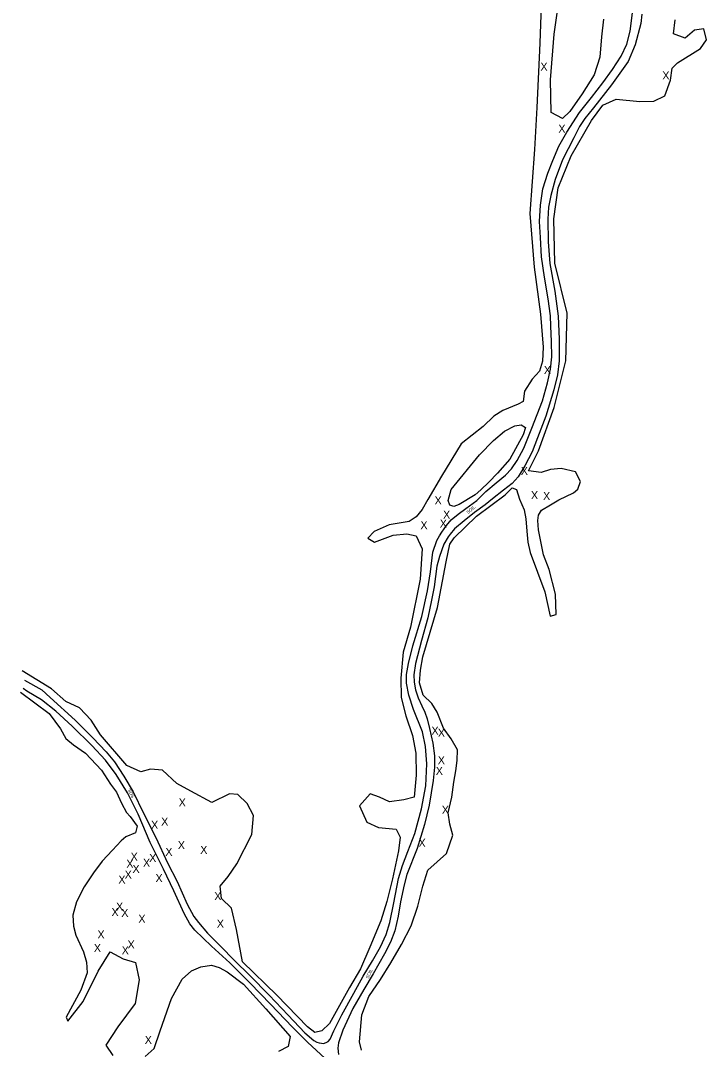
# Model space of a CAD drawing. Extents: x 2030130 to 2036320, y 723205 to 762423.
# Drawn here: x 2031084 to 2031941, y 749317 to 750602 of the extents above; entities that cross this region are included whole.
import ezdxf

# ---------------------------------------------------------------- set-up
doc = ezdxf.new("R2010")
doc.units = 0
for name, color, linetype in [('Draft_Station Labels Major', 7, 'Continuous'), ('Draft_Station Tics Major', 7, 'Continuous'), ('Old_Level_23', 7, 'Continuous')]:
    doc.layers.add(name, color=color, linetype=linetype)

msp = doc.modelspace()

# ---------------------------------------------------------------- linework, layer by layer
at = {"layer": 'Draft_Station Labels Major'}
for points in [[(2031610.3, 749963), (2031616, 749971.2), (2031622.1, 749978.2), (2031630.6, 749985.2), (2031640.2, 749992.3), (2031653.8, 750002.5), (2031665.1, 750013.8), (2031678.3, 750024.7), (2031689.6, 750034.1), (2031697.4, 750041.9), (2031704.2, 750052.6), (2031712.5, 750067.7), (2031722.7, 750092.8), (2031735.8, 750126.8), (2031742.2, 750149.6), (2031746.1, 750166.5), (2031747.6, 750181.8), (2031747.4, 750200.9), (2031746.5, 750220.4), (2031745.8, 750233.2), (2031742.9, 750254.2), (2031738.6, 750281.2), (2031734.8, 750307), (2031733.3, 750330.9), (2031732.4, 750351.1), (2031733.7, 750371.2), (2031736.5, 750391.9), (2031742.7, 750411.2), (2031748.9, 750427.1), (2031756.5, 750445.2), (2031766.4, 750462.5), (2031782.2, 750487.2), (2031797.4, 750505.7), (2031811.2, 750524.3), (2031823.3, 750540.9), (2031834.1, 750557.5), (2031841.4, 750572.3), (2031845.6, 750588.6), (2031848.3, 750611.5)], [(2031859.9, 750609.8), (2031858.7, 750598.1), (2031851.9, 750571.5), (2031842.9, 750550.6), (2031822.3, 750521.7), (2031799.7, 750492.8), (2031789, 750479.4), (2031782.1, 750469.8), (2031775, 750455.5), (2031761.1, 750428), (2031751.7, 750403.3), (2031746.3, 750383.4), (2031743.6, 750369), (2031742.7, 750353.7), (2031742.9, 750325.6), (2031745.3, 750298.4), (2031751.6, 750264.1), (2031755.4, 750232.6), (2031757, 750204.1), (2031757, 750176.7), (2031754.7, 750159.6), (2031750.3, 750140.7), (2031740.1, 750107.9), (2031729.8, 750080.6), (2031723.1, 750063.2), (2031713.8, 750045.9), (2031705.8, 750031.9), (2031698.1, 750023.7), (2031687.2, 750015.5), (2031673.5, 750004.6), (2031664.2, 749996.9), (2031650.9, 749987.6), (2031638, 749976.9), (2031626.1, 749967.1), (2031620.6, 749960.3), (2031618.2, 749956.9)], [(2031088.9, 749778), (2031110.7, 749765.8), (2031121.1, 749756.5), (2031152, 749728.2), (2031174.1, 749706.2), (2031191, 749688.7), (2031201.2, 749675.9), (2031213.1, 749658.2), (2031224.6, 749638.6), (2031237.4, 749612.1), (2031252.8, 749581.7), (2031267.5, 749550), (2031279.6, 749526.7), (2031291.9, 749498.1), (2031300.5, 749482.8), (2031306.4, 749475.4), (2031317.4, 749462), (2031333.8, 749445.9), (2031351.3, 749428.1), (2031370.5, 749409), (2031394.4, 749384.7), (2031418.1, 749359.5), (2031439, 749337.7), (2031450.3, 749327.9), (2031453.9, 749326), (2031456.8, 749325), (2031460.1, 749324.5), (2031462.6, 749324.4), (2031465.6, 749325.4), (2031468.2, 749326.6), (2031470.7, 749329.6), (2031475.5, 749340.2), (2031485.2, 749360.1), (2031500.1, 749387.1), (2031512.1, 749408.5), (2031523.8, 749427.4), (2031533.5, 749444.8), (2031540.6, 749460.5), (2031545.3, 749475.2), (2031550.2, 749500.1), (2031556.1, 749530.5), (2031560.9, 749546.5), (2031567.6, 749564.2), (2031576.6, 749586.6), (2031584.8, 749617.5), (2031590.2, 749646), (2031591.7, 749673.7), (2031590, 749695.3), (2031585.9, 749713.6), (2031574.7, 749741.3), (2031569.2, 749759.2), (2031566.1, 749774.3), (2031566, 749785), (2031568.6, 749798.8), (2031574.2, 749820.8), (2031585.2, 749857.5), (2031592.4, 749889.7), (2031596, 749913.5), (2031599, 749937.9), (2031604.1, 749952.5), (2031607.4, 749958.3), (2031610.3, 749963)], [(2031618.2, 749956.9), (2031612.8, 749947.8), (2031607.3, 749932.7), (2031604.1, 749920.4), (2031600.7, 749894.6), (2031597.2, 749878.1), (2031592.6, 749856), (2031585, 749827.8), (2031577.5, 749798.9), (2031575.3, 749784.8), (2031575.5, 749775.5), (2031577.3, 749766.1), (2031580.8, 749755.9), (2031585.1, 749745.8), (2031589.2, 749737.9), (2031592, 749729.8), (2031594.8, 749717.7), (2031599.1, 749699.3), (2031601.1, 749683.7), (2031601.1, 749669.4), (2031599.5, 749652.8), (2031594.5, 749621.9), (2031588.7, 749597.8), (2031579.6, 749568), (2031566.7, 749535.5), (2031563, 749522.4), (2031558.7, 749501.2), (2031555.5, 749483.1), (2031551.6, 749464.9), (2031546.3, 749451), (2031538.6, 749436.2), (2031524.6, 749411.2), (2031512.7, 749391.7), (2031499, 749367.8), (2031486.7, 749340.8), (2031481, 749325), (2031480.3, 749318.3), (2031481.2, 749310.7)], [(2031464.2, 749305.8), (2031442.7, 749325.6), (2031423.8, 749344.8), (2031396.2, 749373.5), (2031370.9, 749399.6), (2031345.4, 749424.9), (2031322.5, 749446), (2031301.8, 749465.8), (2031295.2, 749473.9), (2031288.4, 749486.7), (2031275.5, 749515), (2031262.3, 749541.9), (2031245.9, 749575.4), (2031230.7, 749610.5), (2031217.4, 749637.4), (2031203.3, 749660.2), (2031190, 749678.3), (2031172.8, 749696.3), (2031148.5, 749720.6), (2031128.1, 749739.2), (2031110.2, 749753.6), (2031091.9, 749764.1), (2031087, 749767.7)]]:
    msp.add_lwpolyline(points, dxfattribs=at)
at = {"layer": 'Draft_Station Tics Major'}
for points in [[(2031736.2, 750667.6), (2031732.7, 750573.7), (2031729, 750493.5), (2031725.9, 750440.9), (2031720.1, 750361.1), (2031725.7, 750294), (2031733.7, 750235.2), (2031736.9, 750193.8), (2031736, 750176.6), (2031732.1, 750163.8), (2031722.9, 750153.9), (2031713.5, 750138.9), (2031711.7, 750126.3), (2031705.7, 750122.9), (2031686.5, 750114.9), (2031675.2, 750108), (2031661.8, 750095), (2031634.4, 750073.1), (2031609.8, 750033), (2031592.8, 750003.6), (2031585.5, 749991.1), (2031578.1, 749981.9), (2031569.4, 749976.1), (2031544.3, 749971.9)], [(2031812.3, 750603.5), (2031809.7, 750581.4), (2031807.7, 750556.4), (2031800.5, 750534.2), (2031785.7, 750510.2), (2031770.2, 750488.4), (2031760.8, 750479.6), (2031746.8, 750486.9), (2031745.8, 750528), (2031750.4, 750585), (2031755.5, 750619.7)], [(2031737.1, 749934.6), (2031730.9, 749965.9), (2031730.3, 749977.3), (2031731, 749984.3), (2031734.8, 749990.3), (2031745.9, 749996.9), (2031756.3, 750003.4), (2031774.7, 750012), (2031780.3, 750016.5), (2031783.6, 750026.3), (2031777.3, 750038.4), (2031759.2, 750042.6), (2031746, 750041.2), (2031734.3, 750037.4), (2031718.6, 750039.5), (2031731.2, 750064.6), (2031750.5, 750118.5), (2031765.2, 750177), (2031766.8, 750236.5), (2031751.6, 750299), (2031750.2, 750354.4), (2031755.5, 750393), (2031771.7, 750432.9), (2031797.2, 750477.2), (2031811.5, 750496.2), (2031828.2, 750503.6), (2031857.5, 750500.7), (2031874.9, 750501.4), (2031888.8, 750508), (2031896, 750527.4), (2031898, 750542.4), (2031904.8, 750549.1), (2031933.2, 750567.1), (2031940.8, 750578), (2031937.5, 750591.5), (2031925.7, 750589.8), (2031914.3, 750580), (2031899.7, 750585.2), (2031901.7, 750603)], [(2031622.1, 750016), (2031657.5, 750059.5), (2031674.7, 750077.2), (2031688.4, 750089), (2031701.5, 750095.7), (2031709.4, 750096.8), (2031714.7, 750093.8), (2031711.9, 750084.5), (2031695.1, 750054.2), (2031679.9, 750036.4), (2031668.8, 750025.2), (2031659.1, 750015.7), (2031651.8, 750009.6)], [(2031651.8, 750009.6), (2031631.9, 749997.5), (2031625.3, 749995.1), (2031620.2, 749996.6), (2031618.2, 750002.4), (2031622.1, 750016)], [(2031625.5, 749956), (2031653.4, 749982.9), (2031689.4, 750009.4), (2031698.2, 750018.4), (2031703.6, 750016.4), (2031707.3, 750004.2), (2031713.3, 749990.8), (2031715, 749979.4), (2031716.6, 749964.1), (2031717.7, 749950.6), (2031720.8, 749937.4)], [(2031544.3, 749971.9), (2031525.9, 749963.6), (2031517.6, 749955.4), (2031526.1, 749950.3), (2031549.5, 749959.3), (2031566.5, 749960.8), (2031578.1, 749958.4), (2031585.6, 749941.9), (2031583.2, 749904.2), (2031571, 749844.2), (2031561.9, 749813.2), (2031559, 749780.4), (2031559.5, 749756.6), (2031565.1, 749733.7), (2031573.7, 749708.8), (2031577.9, 749686.8), (2031578.3, 749659.4), (2031575.5, 749632.1), (2031562.7, 749628.4), (2031544.8, 749626), (2031532.3, 749632.1), (2031520.9, 749636.2), (2031507.5, 749621), (2031516.6, 749600.8), (2031531.3, 749594.1), (2031553.3, 749592.1), (2031558.3, 749582), (2031556.3, 749565), (2031548.5, 749530), (2031541.4, 749501.4), (2031533.9, 749477.6), (2031520.2, 749444.4), (2031508.5, 749417.3), (2031494.7, 749394.1), (2031469.8, 749349.3), (2031460.5, 749340), (2031451.7, 749337.8), (2031442.6, 749345), (2031404.1, 749384.6), (2031361, 749426.3), (2031353.8, 749466.8), (2031347.4, 749493.2), (2031334.9, 749505.4), (2031333.2, 749520.9), (2031343.1, 749533), (2031354.2, 749548.8), (2031372.8, 749585.2), (2031374.9, 749609), (2031367.2, 749623.8), (2031355.4, 749635.4), (2031344.8, 749635.9), (2031322.7, 749625.4), (2031296.5, 749639.6), (2031279.2, 749649.1), (2031261.3, 749665.8), (2031246.4, 749666.7), (2031234.2, 749663.6), (2031216.6, 749671.6), (2031183.8, 749709.9), (2031172.2, 749728.1), (2031157.5, 749743.3), (2031140.6, 749751.4), (2031122.4, 749767.3), (2031086, 749789.5)], [(2031510, 749316.1), (2031507.2, 749326.2), (2031510.2, 749359.9), (2031519, 749382.9), (2031533.6, 749404.2), (2031546.4, 749424.8), (2031560, 749448), (2031572.1, 749471.2), (2031580.4, 749495.9), (2031586.4, 749520.6), (2031592.7, 749540.7), (2031616.2, 749561.6), (2031623.8, 749584.4), (2031620.1, 749598), (2031618.1, 749612.2), (2031622.7, 749632.1), (2031625.1, 749650.7), (2031627.9, 749664.6), (2031629.6, 749677.6), (2031630, 749690.9), (2031621.7, 749704.6), (2031612.2, 749718.2), (2031604.3, 749738.2), (2031597.6, 749749), (2031587, 749759.5), (2031582.5, 749774.6), (2031583.4, 749790.6), (2031586.5, 749807.3), (2031604.9, 749869), (2031615.7, 749925.7), (2031620.1, 749948), (2031625.5, 749956)], [(2031720.8, 749937.4), (2031738.9, 749888.4), (2031745.4, 749858.1), (2031752.9, 749859.9), (2031752.3, 749885.5), (2031744.2, 749916.4), (2031737.1, 749934.6)], [(2031083.9, 749763.1), (2031119.5, 749736.6), (2031133.8, 749717.2), (2031140.3, 749705.2), (2031150.2, 749697.2), (2031165, 749687), (2031184.9, 749665.5), (2031196.1, 749648), (2031203.9, 749638.1), (2031209.9, 749624.3), (2031216.4, 749612.6), (2031220.8, 749607.9), (2031229.7, 749595.6), (2031227.6, 749587.3), (2031215.6, 749582.3), (2031209.8, 749577.3), (2031198.9, 749565.7), (2031185.8, 749552), (2031174.9, 749537.4), (2031163.5, 749519.9), (2031153.8, 749501.1), (2031149.1, 749484.6), (2031150.1, 749470.9), (2031152.8, 749459.6), (2031162.7, 749438.7), (2031166.5, 749426), (2031167.1, 749412.6), (2031159.3, 749390.7), (2031140.8, 749357), (2031142.9, 749352.2), (2031162.2, 749376.7), (2031180.8, 749414.7), (2031195.8, 749438.9), (2031212.1, 749430.1), (2031227.5, 749425.4), (2031232, 749403.9), (2031227.1, 749374.1), (2031205.4, 749345), (2031190.5, 749322), (2031199.2, 749309.3)], [(2031239.6, 749307.9), (2031251, 749317.9), (2031258.3, 749339.9), (2031272.5, 749380.5), (2031285.8, 749404.6), (2031297.5, 749414.8), (2031309.1, 749420), (2031322.5, 749421.9), (2031331.9, 749419.3), (2031341.9, 749413.6), (2031362.6, 749398.2), (2031390.4, 749367.4), (2031420.7, 749333.1), (2031418.2, 749320.4), (2031406.1, 749314.1)]]:
    msp.add_lwpolyline(points, dxfattribs=at)

# ---------------------------------------------------------------- texts
for p in [(2031733.4, 750539.3), (2031885.7, 750528.4), (2031755.8, 750461.8), (2031737.7, 750160.5), (2031708.9, 750034.4), (2031601.2, 749997.6), (2031721.6, 750004.2), (2031736.7, 750003.1), (2031611.8, 749979.8), (2031583.5, 749966.6), (2031607.7, 749968.7), (2031597.3, 749709.9), (2031605.3, 749707.3), (2031605.2, 749673.1), (2031602.7, 749659.7), (2031281.5, 749620.4), (2031610.2, 749611.1), (2031259.6, 749596.4), (2031247, 749592.4), (2031581.1, 749569.9), (2031264.8, 749558.6), (2031280.4, 749567), (2031308.4, 749561.1), (2031216.1, 749543.8), (2031221.4, 749552.6), (2031236.9, 749545), (2031244.6, 749551), (2031214, 749530.2), (2031223.8, 749537.3), (2031206.1, 749524), (2031252.5, 749525.8), (2031325.9, 749503.3), (2031197.5, 749483.4), (2031203.2, 749490.3), (2031209.8, 749482.4), (2031231.1, 749475), (2031329.1, 749468.9), (2031180, 749455.5), (2031217.6, 749442.9), (2031175.5, 749438.6), (2031210.3, 749435.6), (2031239.1, 749323.8)]:
    msp.add_text('X', height=10, dxfattribs=at).set_placement(p)
at = {"layer": 'Old_Level_23'}
for rotation, p in [(39.8444, (2031643, 749985.5)), (119.7584, (2031226.6, 749632.6)), (63.7653, (2031518.6, 749405))]:
    msp.add_text('SOIL', height=4, rotation=rotation, dxfattribs=at).set_placement(p)

doc.saveas('drawing.dxf')
